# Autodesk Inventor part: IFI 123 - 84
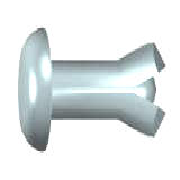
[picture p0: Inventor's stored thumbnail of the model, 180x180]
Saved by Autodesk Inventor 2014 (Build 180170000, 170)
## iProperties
Created: 2013-02
Part Number: IFI 123 - 84
Material: Steel, Mild
Description: Protruding Head Drive Pin Blind Rivet - Inch
Document SubType Name: Modeling
Standard: IFI 123
Designer: Dave
Standard Revision: 2003
Standards Organization: ANSI
Language: en-US
Size Designation: 84
Categories: <MemberInstance><Categories><Category DisplayName="Fasteners" InternalName="e4da775c-781d-43d5-af7c-5136215cf5a6" Mnemonic="FSTN"><Category DisplayName="Rivets"
Density: 1 g/cm^3
Appearance: Steel
IsCustomPart: 1
Author: Dave
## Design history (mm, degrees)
sketch "Sketch1"
  geometry: L1 (0, 0)-(0, 6.667); L2 (0, 6.667)-(2.972, 6.667); L3 (2.972, 3.175)-(5.767, 3.175); L4 (5.767, 3.175)-(11.816, 6.667); L5 (11.816, 6.667)-(11.816, 0); L6 (11.816, 0)-(0, 0); L7 (-2.757, 0)-(16.541, 0) reference; L8 (0, -0.665)-(0, 3.993) reference; L9 (2.972, 3.175)-(2.972, 6.667)
  constraints: 14 end point, 3 parallel, 2 collinear, 2 perpendicular, 1 vertical
  dimensions: "d0" = 6.35 diameter of L3 L6 (= NND); "d1" = 13.335 diameter of L2 L6 (= KOD); "d2" = 30 deg angle of L4 L6; "d3" = 13.335 diameter of L4.end L6 (= KOD); "d18" = 2.9718 distance between parallel lines of L9 L1 (= KOH); "d20" = 2.795 distance of L3.start L3.end (computed from KLG)
revolve "Body" sketch "Sketch1" stored, may be unused: angle "d10" = 90 deg
sketch "Sketch2"
  geometry: L1 (5.767, 0)-(11.816, 3.492); L2 (11.816, 3.492)-(11.816, 0); L3 (5.767, 0)-(11.816, 0); L4 (10.168, 0)-(14.387, 0) reference; L5 (5.767, 3.175)-(11.816, 6.667) reference; L6 (11.816, -6.668)-(11.816, 6.667) reference; L7 (5.767, -3.175)-(5.767, 3.175) reference; L8 (5.767, 0)-(11.816, -3.492); L9 (11.816, -3.492)-(11.816, 0)
  constraints: 10 end point, 2 collinear, 1 midpoint, 1 parallel, 1 perpendicular, 1 symmetric about line, 1 vertical, 2 other
extrude "Cut1" cut sketch "Sketch2" taper "d4" = 0 deg; stored distance "d11" = 10
pattern_circular "Cuts1" dims angle "d6" = 90 deg
node "IDS_WORKPLANE{1}"
sketch "Sketch3"
  geometry: L1 (0, -9.335)-(0, 9.335) reference; L2 (-9.335, 0)-(9.335, 0) reference; L3 (-6.668, 0.318)-(-0.317, 0.318); L4 (-0.317, 0.318)-(-0.317, 6.668); L5 (-0.317, 6.668)-(0, 6.668); L6 (-6.668, 0.318)-(-6.668, 0); L7 (0.317, 6.668)-(0, 6.668); L8 (0.317, 0.318)-(0.317, 6.668); L9 (6.668, 0.318)-(0.317, 0.318); L10 (6.668, 0.318)-(6.668, 0); L11 (-6.668, -0.317)-(-0.317, -0.317); L12 (-0.317, -0.317)-(-0.317, -6.667); L13 (0.317, -0.317)-(0.317, -6.667); L14 (6.668, -0.317)-(0.317, -0.317); L15 (0.317, -6.667)-(0, -6.667); L16 (-0.317, -6.667)-(0, -6.667); L17 (-6.668, -0.317)-(-6.668, 0); L18 (6.668, -0.317)-(6.668, 0); C1 r 6.668 at (0, 0) reference
  constraints: 32 end point, 11 symmetric about line, 2 parallel, 2 perpendicular, 2 point on line, 2 tangent, 12 other
  dimensions: "d8" = 0.3175 distance between parallel lines of L4 L1 (= 0.05 x NND); "d9" = 0.3175 distance between parallel lines of L3 L2 (= 0.05 x NND)
extrude "Cut2" cut sketch "Sketch3" taper "d12" = 0 deg; stored distance "d19" = 10
node "IDS_WORKPLANE{2}"
sketch "Sketch4"
  geometry: L1 (0, 1.728)-(0, 1.547) reference; L2 (5.499, -4.939)-(0, -4.939) reference; L3 (0, 0)-(0, 2.395); L4 (0, 2.395)-(2.794, 2.395); L5 (2.794, 2.395)-(2.794, 0); L6 (2.794, 0)-(0, 0)
  constraints: 8 end point, 3 perpendicular, 1 parallel
  dimensions: "d26" = 7.33425 distance between parallel lines of L2 L4 (= 0.55 x KOD); "d27" = 2.794 distance between parallel lines of L5 L3 (= KLG)
extrude "Cut3" cut sketch "Sketch4" taper "d13" = 0 deg; stored distance "d22" = 10
pattern_circular "Cuts2" dims angle "d16" = 90 deg
sketch "Sketch5"
  geometry: L1 (3.67, 0.318)-(3.67, -0.317) reference; L2 (3.67, 2.381)-(6.317, 2.381); L3 (3.67, 0)-(8.698, 0); L4 (3.67, 0.318)-(5.767, 0.318) reference; L5 (2.197, 0)-(14.197, 0) reference; L6 (3.67, 2.381)-(3.67, 0); L7 (6.317, 0.318)-(6.317, 3.478) reference; A1 r 2.381 centre (6.317, 0) between (8.698, 0) and (6.317, 2.381)
  constraints: 6 end point, 2 collinear, 2 perpendicular, 2 point on circle, 2 point on line, 1 centre point, 1 tangent
  dimensions: "d17" = 4.7625 diameter of L2 L3 (= 0.75 x NND)
revolve "Pin" sketch "Sketch5" stored, may be unused: angle "d28" = 90 deg
body "Solid1"
fillet "Fillet1" dims "d21" = 2.9718 (= KOH)
other parameters: "KLG" = 2.794 [user parameter; used in 3 equation terms], "NND" = 6.35 [user parameter; used in 4 equation terms], "KOD" = 13.335 [user parameter; used in 3 equation terms], "KOH" = 2.9718 [user parameter; used in 3 equation terms], "d7" = -3.6703 (= -KOH - 0.25 x KLG), "d23" = 0, "d24" = 0, "KLGMAX" = 4.3434 [user parameter], "KLGMIN" = 2.794 [user parameter]
